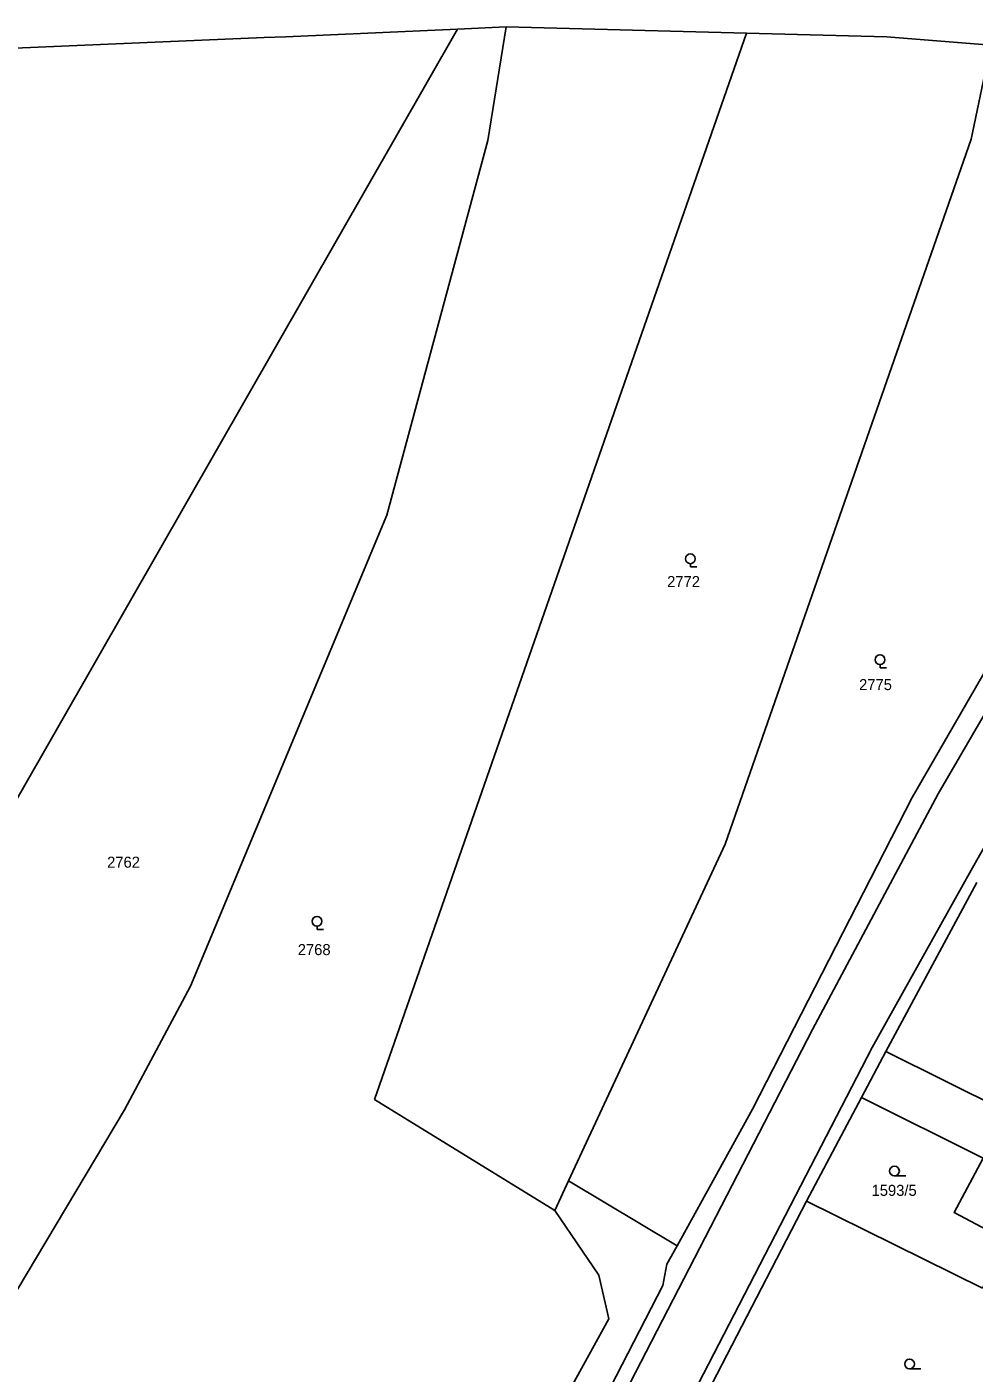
# Model space of a CAD drawing. Extents: x -679220 to -673243, y -1075091 to -1066557.
# Drawn here: x -677779.5 to -677633.6, y -1071612.6 to -1071405.2 of the extents above; entities that cross this region are included whole.
import ezdxf

# ---------------------------------------------------------------- set-up
doc = ezdxf.new("R2010")
doc.units = 0
for name, color, linetype in [('Hranice parcel', 7, 'Continuous'), ('Parcelní čísla', 7, 'Continuous'), ('Vnitřní kresba', 7, 'Continuous'), ('Značky kultur', 7, 'Continuous')]:
    doc.layers.add(name, color=color, linetype=linetype)

msp = doc.modelspace()

# ---------------------------------------------------------------- linework, layer by layer
at = {"layer": 'Hranice parcel'}
for p, q in [((-677713.2, -1071405.54), (-677705.67, -1071405.2)), ((-677705.67, -1071405.2), (-677668.67, -1071406.15)), ((-677647.17, -1071563.08), (-677633.15, -1071537.04)), ((-677650.93, -1071570.15), (-677647.17, -1071563.08)), ((-677611.33, -1071580.93), (-677647.17, -1071563.08)), ((-677659.4, -1071586.1), (-677650.93, -1071570.15)), ((-677696.09, -1071583.01), (-677698.2, -1071587.54)), ((-677696.09, -1071583.01), (-677679.36, -1071592.98)), ((-677675.7, -1071617.62), (-677659.4, -1071586.1)), ((-677632.29, -1071599.54), (-677659.4, -1071586.1))]:
    msp.add_line(p, q, dxfattribs=at)
for points in [[(-677705.67, -1071405.2), (-677708.49, -1071422.7), (-677724.04, -1071480.43), (-677754.3, -1071553.01), (-677764.49, -1071572.04), (-677793.05, -1071619.95)], [(-677793.05, -1071619.95), (-677824.5, -1071600.05), (-677768.85, -1071502.8), (-677713.2, -1071405.54)], [(-677812.3, -1071408.79), (-677793.42, -1071409), (-677742.98, -1071406.85), (-677739.63, -1071406.72), (-677713.2, -1071405.54)], [(-677668.67, -1071406.15), (-677725.96, -1071570.45), (-677698.2, -1071587.54)], [(-677668.67, -1071406.15), (-677647.03, -1071406.71), (-677631.04, -1071408.03)], [(-677631.04, -1071408.03), (-677634.06, -1071422.51), (-677671.93, -1071531.12), (-677696.09, -1071583.01)], [(-677581.06, -1071413.63), (-677589.62, -1071430.98), (-677623.81, -1071490.51), (-677643.12, -1071523.94), (-677667.72, -1071571.95), (-677679.36, -1071592.98)], [(-677650.93, -1071570.15), (-677632.21, -1071579.49), (-677636.67, -1071587.87), (-677628.27, -1071592.32), (-677632.29, -1071599.54)], [(-677698.2, -1071587.54), (-677691.4, -1071597.52), (-677689.84, -1071604.27), (-677722.95, -1071664.32)], [(-677679.36, -1071592.98), (-677680.93, -1071595.81), (-677681.57, -1071599.11), (-677713.84, -1071661.87), (-677715.32, -1071664.31), (-677717.06, -1071668.11), (-677734.17, -1071699.43)]]:
    msp.add_lwpolyline(points, dxfattribs=at)
at = {"layer": 'Vnitřní kresba'}
for p, q in [((-677639.12, -1071523.36), (-677620.95, -1071491.99)), ((-677612.34, -1071496.67), (-677634.05, -1071535.11)), ((-677658.49, -1071559.68), (-677639.12, -1071523.36)), ((-677634.05, -1071535.11), (-677649.28, -1071562.45)), ((-677658.49, -1071559.68), (-677713.36, -1071666.01)), ((-677704.66, -1071669.46), (-677649.28, -1071562.45))]:
    msp.add_line(p, q, dxfattribs=at)
at = {"layer": 'Značky kultur'}
for p, q in [((-677677.3, -1071487.9), (-677677.3, -1071488.4)), ((-677677.3, -1071488.4), (-677676.3, -1071488.4)), ((-677648.09, -1071503.44), (-677648.09, -1071503.94)), ((-677648.09, -1071503.94), (-677647.09, -1071503.94)), ((-677734.81, -1071543.74), (-677734.81, -1071544.24)), ((-677734.81, -1071544.24), (-677733.81, -1071544.24)), ((-677645.86, -1071582.23), (-677644.11, -1071582.23)), ((-677643.54, -1071611.95), (-677641.79, -1071611.95))]:
    msp.add_line(p, q, dxfattribs=at)
for centre in [(-677677.3, -1071487.15), (-677648.09, -1071502.69), (-677734.81, -1071542.99), (-677645.86, -1071581.48), (-677643.54, -1071611.2)]:
    msp.add_circle(centre, 0.75, dxfattribs=at)

# ---------------------------------------------------------------- texts
at = {"layer": 'Parcelní čísla'}
for s, p in [('2772', (-677680.88, -1071491.5)), ('2775', (-677651.31, -1071507.38)), ('2762', (-677767.15, -1071534.74)), ('2768', (-677737.78, -1071548.21)), ('1593/5', (-677649.39, -1071585.3))]:
    msp.add_text(s, height=1.7, dxfattribs=at).set_placement(p)

doc.saveas('drawing.dxf')
